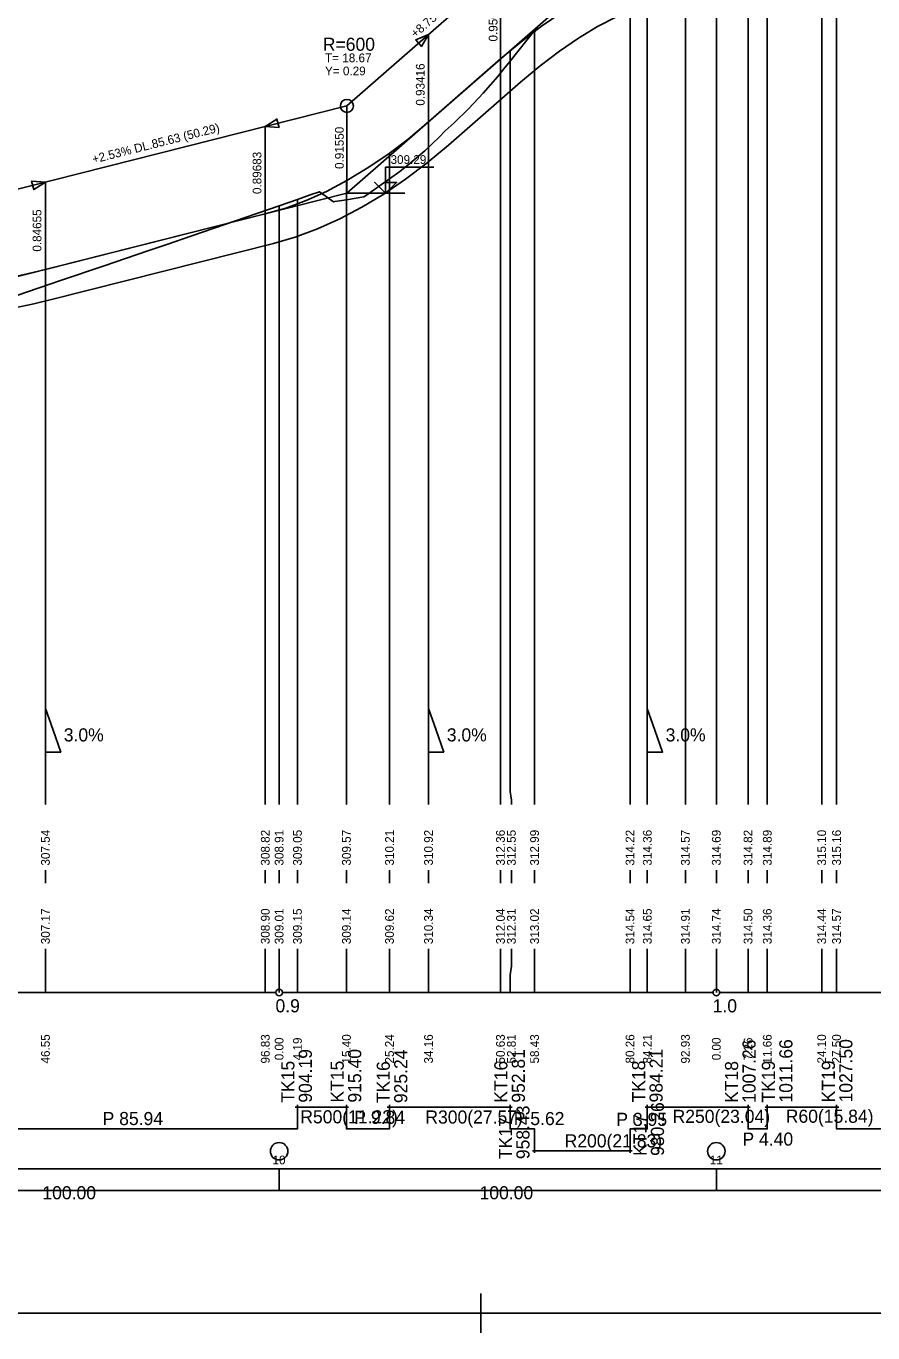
# Model space of a CAD drawing. Extents: x 1301 to 1448, y 183 to 228.
# Drawn here: x 1395.56 to 1414.92, y 182.54 to 212.44 of the extents above; entities that cross this region are included whole.
import ezdxf

# ---------------------------------------------------------------- set-up
doc = ezdxf.new("R2010")
doc.units = 0
for name, color, linetype in [('KOTA', 7, 'Continuous'), ('NOVY_STAV', 7, 'Continuous'), ('NS_OBLOUK', 7, 'Continuous'), ('REZY_PO', 7, 'Continuous'), ('SESTAVY_REZU_PO', 7, 'Continuous'), ('SKLONOVE_POMERY', 7, 'Continuous'), ('SMEROVE_POMERY', 7, 'Continuous'), ('SMEROVE_POMERY_KOD', 7, 'Continuous'), ('SVK_STAT', 7, 'Continuous'), ('u_drenaz', 7, 'Continuous'), ('u_pricne_rezy', 7, 'Continuous'), ('x_formát_rám', 7, 'Continuous')]:
    doc.layers.add(name, color=color, linetype=linetype)

msp = doc.modelspace()

# ---------------------------------------------------------------- linework, layer by layer
at = {"layer": 'KOTA'}
msp.add_line((1402.893, 208.614), (1404.219, 208.614), dxfattribs=at)
for points in [[(1403.779, 208.614), (1403.529, 208.864), (1403.779, 208.614), (1403.779, 209.214), (1404.879, 209.214)], [(1403.779, 208.864), (1403.779, 208.614), (1404.029, 208.864), (1403.779, 208.864)], [(1403.779, 208.614), (1404.029, 208.864), (1403.779, 208.864)], [(1402.893, 208.614), (1402.893, 208.614)], [(1403.779, 208.614), (1403.779, 208.614)]]:
    msp.add_lwpolyline(points, dxfattribs=at)
at = {"layer": 'NOVY_STAV'}
for points in [[(1402.893, 210.614), (1408.521, 215.539)], [(1371.343, 199.496), (1372.956, 201.369), (1382.912, 202.588), (1387.709, 206.246), (1394.33, 206.448), (1402.893, 208.614), (1408.521, 213.539), (1416.937, 214.971), (1425.443, 212.807)], [(1395.164, 206.682), (1395.581, 206.77), (1395.998, 206.87), (1401.026, 208.142), (1401.493, 208.278), (1401.959, 208.45), (1402.426, 208.659), (1402.893, 208.904), (1403.359, 209.186), (1403.826, 209.503), (1404.293, 209.857), (1404.759, 210.247), (1406.406, 211.688), (1406.876, 212.081), (1407.346, 212.437), (1407.816, 212.757)], [(1394.33, 208.448), (1402.893, 210.614)], [(1402.893, 208.614), (1402.893, 210.614)]]:
    msp.add_lwpolyline(points, dxfattribs=at)
msp.add_circle((1402.893, 210.614), 0.15, dxfattribs=at)
at = {"layer": 'NS_OBLOUK'}
for points in [[(1406.406, 211.688), (1406.406, 213.688)], [(1404.599, 211.975), (1404.759, 212.247), (1404.468, 212.125), (1404.599, 211.975)], [(1404.759, 210.247), (1404.759, 212.247)], [(1401.026, 210.142), (1401.341, 210.118), (1401.292, 210.312), (1401.026, 210.142)], [(1401.026, 208.142), (1401.026, 210.142)], [(1395.731, 208.699), (1395.998, 208.87), (1395.682, 208.893), (1395.731, 208.699)], [(1395.998, 206.87), (1395.998, 208.87)]]:
    msp.add_lwpolyline(points, dxfattribs=at)
for points in [[(1404.759, 212.247), (1404.468, 212.125), (1404.599, 211.975)], [(1401.026, 210.142), (1401.292, 210.312), (1401.341, 210.118)], [(1395.998, 208.87), (1395.682, 208.893), (1395.731, 208.699)]]:
    msp.add_lwpolyline(points, close=True, dxfattribs=at)
at = {"layer": 'REZY_PO'}
msp.add_lwpolyline([(1395.343, 206.278), (1396.343, 206.618), (1397.343, 206.957), (1398.343, 207.297), (1398.773, 207.443), (1399.343, 207.64), (1400.343, 207.986), (1401.343, 208.331), (1401.343, 208.331), (1401.761, 208.475), (1401.761, 208.475), (1401.761, 208.475), (1402.052, 208.576), (1402.264, 208.651), (1402.343, 208.594), (1402.588, 208.42), (1402.613, 208.424), (1402.883, 208.468), (1402.883, 208.468), (1402.883, 208.468), (1403.282, 208.531), (1403.343, 208.573), (1403.867, 208.942), (1403.867, 208.942), (1403.867, 208.942), (1404.105, 209.114), (1404.343, 209.304), (1404.676, 209.59), (1405.009, 209.906), (1405.143, 210.044), (1405.343, 210.225), (1405.676, 210.55), (1406.009, 210.906), (1406.343, 211.29), (1406.483, 211.46), (1406.624, 211.635), (1406.624, 211.635), (1406.624, 211.635), (1407.186, 212.343), (1407.264, 212.441)], dxfattribs=at)
at = {"layer": 'SESTAVY_REZU_PO'}
for points in [[(1391.418, 190.326), (1401.268, 190.326)], [(1401.418, 190.326), (1411.268, 190.326)], [(1411.418, 190.326), (1421.268, 190.326)]]:
    msp.add_lwpolyline(points, dxfattribs=at)
for centre in [(1401.343, 190.326), (1411.343, 190.326)]:
    msp.add_circle(centre, 0.075, dxfattribs=at)
at = {"layer": 'SKLONOVE_POMERY'}
for points in [[(1395.998, 195.826), (1395.998, 196.826), (1395.998, 196.826), (1396.173, 196.326), (1396.348, 195.826), (1395.998, 195.826)], [(1404.759, 195.826), (1404.759, 196.826), (1404.759, 196.826), (1404.934, 196.326), (1405.109, 195.826), (1404.759, 195.826)], [(1409.764, 195.826), (1409.764, 196.826), (1409.764, 196.826), (1409.939, 196.326), (1410.114, 195.826), (1409.764, 195.826)]]:
    msp.add_lwpolyline(points, dxfattribs=at)
at = {"layer": 'SMEROVE_POMERY'}
msp.add_lwpolyline([(1393.167, 187.204), (1401.761, 187.204), (1401.761, 187.704), (1402.883, 187.704), (1402.883, 187.204), (1403.867, 187.204), (1403.867, 187.704), (1406.624, 187.704), (1406.624, 187.204), (1407.186, 187.204), (1407.186, 186.704), (1409.369, 186.704), (1409.369, 187.204), (1409.764, 187.204), (1409.764, 187.704), (1412.069, 187.704), (1412.069, 187.204), (1412.509, 187.204), (1412.509, 187.704), (1414.092, 187.704), (1414.092, 187.204), (1416.452, 187.204)], dxfattribs=at)
at = {"layer": 'SMEROVE_POMERY_KOD'}
for points in [[(1401.711, 187.704), (1401.811, 187.704)], [(1401.761, 187.654), (1401.761, 187.754)], [(1402.833, 187.704), (1402.933, 187.704)], [(1402.883, 187.654), (1402.883, 187.754)], [(1403.817, 187.704), (1403.917, 187.704)], [(1403.867, 187.654), (1403.867, 187.754)], [(1406.574, 187.704), (1406.674, 187.704)], [(1406.624, 187.654), (1406.624, 187.754)], [(1409.714, 187.704), (1409.814, 187.704)], [(1409.764, 187.654), (1409.764, 187.754)], [(1412.019, 187.704), (1412.119, 187.704)], [(1412.069, 187.654), (1412.069, 187.754)], [(1412.459, 187.704), (1412.559, 187.704)], [(1412.509, 187.654), (1412.509, 187.754)], [(1414.042, 187.704), (1414.142, 187.704)], [(1414.092, 187.654), (1414.092, 187.754)], [(1407.136, 186.704), (1407.236, 186.704)], [(1407.186, 186.654), (1407.186, 186.754)], [(1409.319, 186.704), (1409.419, 186.704)], [(1409.369, 186.654), (1409.369, 186.754)]]:
    msp.add_lwpolyline(points, dxfattribs=at)
at = {"layer": 'SVK_STAT'}
for points in [[(1413.753, 194.626), (1413.753, 214.429)], [(1414.092, 194.626), (1414.092, 214.482)], [(1410.636, 194.626), (1410.636, 214.236)], [(1412.069, 194.626), (1412.069, 214.143)], [(1412.509, 194.626), (1412.509, 214.218)], [(1409.369, 194.626), (1409.369, 213.868)], [(1409.764, 194.626), (1409.764, 213.977)], [(1411.343, 194.626), (1411.343, 214.07)], [(1407.186, 194.626), (1407.186, 212.343)], [(1406.656, 194.626), (1406.656, 194.726), (1406.624, 194.926), (1406.624, 211.871)], [(1406.406, 194.626), (1406.406, 211.688)], [(1404.759, 194.626), (1404.759, 210.247)], [(1403.867, 194.626), (1403.867, 209.535)], [(1402.883, 194.626), (1402.883, 208.899)], [(1401.761, 194.626), (1401.761, 208.475)], [(1401.026, 194.626), (1401.026, 208.222)], [(1401.343, 194.626), (1401.343, 208.331)], [(1395.998, 194.626), (1395.998, 206.87)], [(1395.998, 192.826), (1395.998, 193.126)], [(1401.026, 192.826), (1401.026, 193.126)], [(1401.343, 192.826), (1401.343, 193.126)], [(1401.761, 192.826), (1401.761, 193.126)], [(1402.883, 192.826), (1402.883, 193.126)], [(1403.867, 192.826), (1403.867, 193.126)], [(1404.759, 192.826), (1404.759, 193.126)], [(1406.406, 192.826), (1406.406, 193.126)], [(1406.656, 192.826), (1406.656, 193.126)], [(1407.186, 192.826), (1407.186, 193.126)], [(1409.369, 192.826), (1409.369, 193.126)], [(1409.764, 192.826), (1409.764, 193.126)], [(1410.636, 192.826), (1410.636, 193.126)], [(1411.343, 192.826), (1411.343, 193.126)], [(1412.069, 192.826), (1412.069, 193.126)], [(1412.509, 192.826), (1412.509, 193.126)], [(1413.753, 192.826), (1413.753, 193.126)], [(1414.092, 192.826), (1414.092, 193.126)], [(1395.998, 190.326), (1395.998, 191.326)], [(1401.026, 190.326), (1401.026, 191.326)], [(1401.343, 190.326), (1401.343, 191.326)], [(1401.761, 190.326), (1401.761, 191.326)], [(1402.883, 190.326), (1402.883, 191.326)], [(1403.867, 190.326), (1403.867, 191.326)], [(1404.759, 190.326), (1404.759, 191.326)], [(1406.406, 190.326), (1406.406, 191.326)], [(1406.624, 190.326), (1406.624, 190.726), (1406.656, 190.926), (1406.656, 191.326)], [(1407.186, 190.326), (1407.186, 191.326)], [(1409.369, 190.326), (1409.369, 191.326)], [(1409.764, 190.326), (1409.764, 191.326)], [(1410.636, 190.326), (1410.636, 191.326)], [(1411.343, 190.326), (1411.343, 191.326)], [(1412.069, 190.326), (1412.069, 191.326)], [(1412.509, 190.326), (1412.509, 191.326)], [(1413.753, 190.326), (1413.753, 191.326)], [(1414.092, 190.326), (1414.092, 191.326)]]:
    msp.add_lwpolyline(points, dxfattribs=at)
at = {"layer": 'u_drenaz'}
msp.add_lwpolyline([(1395.299, 205.995), (1395.734, 206.087), (1396.165, 206.19), (1401.21, 207.466), (1401.712, 207.613), (1402.224, 207.802), (1402.732, 208.029), (1403.236, 208.294), (1403.737, 208.596), (1404.235, 208.935), (1404.729, 209.31), (1405.214, 209.715), (1406.861, 211.156), (1407.312, 211.533), (1407.754, 211.868), (1408.193, 212.167), (1408.628, 212.428), (1409.06, 212.654)], dxfattribs=at)
at = {"layer": 'u_pricne_rezy'}
for points in [[(1311.343, 185.793), (1425.461, 185.793), (1425.461, 186.293), (1311.343, 186.293), (1311.343, 185.793)], [(1401.343, 185.793), (1401.343, 186.293)], [(1411.343, 185.793), (1411.343, 186.293)]]:
    msp.add_lwpolyline(points, dxfattribs=at)
for centre in [(1401.343, 186.693), (1411.343, 186.693)]:
    msp.add_circle(centre, 0.2, dxfattribs=at)
at = {"layer": 'x_formát_rám'}
msp.add_line((1405.954, 182.537), (1405.954, 183.437), dxfattribs=at)
msp.add_lwpolyline([(1300.954, 182.987), (1447.954, 182.987), (1447.954, 227.537), (1300.954, 227.537)], close=True, dxfattribs=at)

# ---------------------------------------------------------------- texts
at = {"layer": 'KOTA'}
msp.add_text('309.29', height=0.2, dxfattribs=at).set_placement((1403.891, 209.287))
at = {"layer": 'NOVY_STAV'}
for s, rotation, p in [('+8.75% DL.56.28 (16.47)', 41.1901, (1404.46, 212.16)), ('+2.53% DL.85.63 (50.29)', 14.1949, (1397.094, 209.293)), (' 0.91550', 90, (1402.82, 209.097))]:
    msp.add_text(s, height=0.2, rotation=rotation, dxfattribs=at).set_placement(p)
at = {"layer": 'NS_OBLOUK'}
for s, p in [(' 0.95063', (1406.337, 212.014)), (' 0.93416', (1404.671, 210.545)), (' 0.89683', (1400.937, 208.523)), (' 0.84655', (1395.905, 207.205))]:
    msp.add_text(s, height=0.2, rotation=90, dxfattribs=at).set_placement(p)
for s, height, p in [('R=600', 0.3, (1402.342, 211.875)), ('T= 18.67', 0.2, (1402.393, 211.614)), ('Y= 0.29', 0.2, (1402.393, 211.314))]:
    msp.add_text(s, height=height, dxfattribs=at).set_placement(p)
at = {"layer": 'SESTAVY_REZU_PO'}
for s, p in [('0.9', (1401.259, 189.871)), ('1.0', (1411.259, 189.871))]:
    msp.add_text(s, height=0.3, dxfattribs=at).set_placement(p)
at = {"layer": 'SKLONOVE_POMERY'}
for p in [(1396.417, 196.071), (1405.178, 196.071), (1410.183, 196.071)]:
    msp.add_text('3.0%', height=0.3, dxfattribs=at).set_placement(p)
at = {"layer": 'SMEROVE_POMERY'}
for s, p in [('P 85.94', (1397.305, 187.291)), ('R500(11.22)', (1401.827, 187.331)), ('P 9.84', (1403.063, 187.319)), ('R300(27.57)', (1404.687, 187.326)), ('P 5.62', (1406.709, 187.291)), ('P 3.95', (1409.056, 187.273)), ('R250(23.04)', (1410.342, 187.341)), ('R60(15.84)', (1412.931, 187.344)), ('R200(21.83)', (1407.873, 186.781)), ('P 4.40', (1411.94, 186.821))]:
    msp.add_text(s, height=0.3, dxfattribs=at).set_placement(p)
at = {"layer": 'SMEROVE_POMERY_KOD'}
for s, p in [('904.19', (1402.092, 187.804)), ('915.40', (1403.221, 187.806)), ('925.24', (1404.274, 187.794)), ('952.81', (1406.964, 187.804)), ('984.21', (1410.115, 187.809)), ('1007.26', (1412.241, 187.799)), ('1011.66', (1413.083, 187.806)), ('1027.50', (1414.455, 187.809)), ('TK15', (1401.692, 187.804)), ('KT15', (1402.821, 187.806)), ('TK16', (1403.874, 187.794)), ('KT16', (1406.564, 187.804)), ('TK18', (1409.715, 187.809)), ('KT18', (1411.841, 187.799)), ('TK19', (1412.683, 187.806)), ('KT19', (1414.055, 187.809)), ('980.26', (1410.146, 186.586)), ('958.43', (1407.069, 186.512)), ('KT17', (1409.746, 186.586)), ('TK17', (1406.669, 186.512))]:
    msp.add_text(s, height=0.3, rotation=90, dxfattribs=at).set_placement(p)
at = {"layer": 'SVK_STAT'}
for s, p in [(' 307.54', (1396.097, 193.156)), (' 308.82', (1401.126, 193.156)), (' 308.91', (1401.442, 193.156)), (' 309.05', (1401.861, 193.156)), (' 309.57', (1402.982, 193.156)), (' 310.21', (1403.967, 193.156)), (' 310.92', (1404.859, 193.156)), (' 312.36', (1406.505, 193.156)), (' 312.55', (1406.755, 193.156)), (' 312.99', (1407.285, 193.156)), (' 314.22', (1409.468, 193.156)), (' 314.36', (1409.864, 193.156)), (' 314.57', (1410.735, 193.156)), (' 314.69', (1411.442, 193.156)), (' 314.82', (1412.168, 193.156)), (' 314.89', (1412.608, 193.156)), (' 315.10', (1413.852, 193.156)), (' 315.16', (1414.192, 193.156)), (' 307.17', (1396.097, 191.356)), (' 308.90', (1401.126, 191.356)), (' 309.01', (1401.442, 191.356)), (' 309.15', (1401.861, 191.356)), (' 309.14', (1402.982, 191.356)), (' 309.62', (1403.967, 191.356)), (' 310.34', (1404.859, 191.356)), (' 312.04', (1406.505, 191.356)), (' 312.31', (1406.755, 191.356)), (' 313.02', (1407.285, 191.356)), (' 314.54', (1409.468, 191.356)), (' 314.65', (1409.864, 191.356)), (' 314.91', (1410.735, 191.356)), (' 314.74', (1411.442, 191.356)), (' 314.50', (1412.168, 191.356)), (' 314.36', (1412.608, 191.356)), (' 314.44', (1413.852, 191.356)), (' 314.57', (1414.192, 191.356)), (' 46.55', (1396.097, 188.626)), (' 96.83', (1401.126, 188.626)), (' 15.40', (1402.982, 188.626)), (' 25.24', (1403.967, 188.626)), (' 34.16', (1404.859, 188.626)), (' 50.63', (1406.505, 188.626)), (' 52.81', (1406.755, 188.626)), (' 58.43', (1407.285, 188.626)), (' 80.26', (1409.468, 188.626)), (' 84.21', (1409.864, 188.626)), (' 92.93', (1410.735, 188.626)), (' 11.66', (1412.608, 188.626)), (' 24.10', (1413.852, 188.626)), (' 27.50', (1414.192, 188.626)), ('  0.00', (1401.442, 188.626)), ('  4.19', (1401.861, 188.626)), ('  0.00', (1411.442, 188.626)), ('  7.26', (1412.168, 188.626))]:
    msp.add_text(s, height=0.2, rotation=90, dxfattribs=at).set_placement(p)
at = {"layer": 'u_pricne_rezy'}
for s, height, p in [('10', 0.2, (1401.192, 186.393)), ('11', 0.2, (1411.192, 186.393)), ('100.00', 0.3, (1395.927, 185.593)), ('100.00', 0.3, (1405.927, 185.593))]:
    msp.add_text(s, height=height, dxfattribs=at).set_placement(p)

doc.saveas('drawing.dxf')
